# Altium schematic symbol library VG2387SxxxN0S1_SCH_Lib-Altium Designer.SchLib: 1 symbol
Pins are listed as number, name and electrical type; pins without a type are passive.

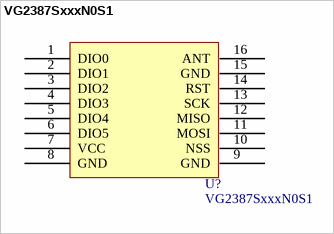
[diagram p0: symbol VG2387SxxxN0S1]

## VG2387SxxxN0S1
designator U?
footprint G238xNS1
footprint G238xNS1_TO
pins: 1 DIO0, 2 DIO1, 3 DIO2, 4 DIO3, 5 DIO4, 6 DIO5, 7 VCC, 8 GND, 9 GND, 10 NSS, 11 MOSI, 12 MISO, 13 SCK, 14 RST, 15 GND, 16 ANT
